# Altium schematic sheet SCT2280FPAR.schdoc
size 127 x 101 mm
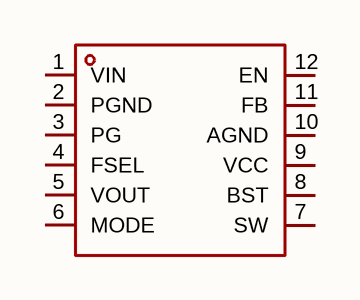
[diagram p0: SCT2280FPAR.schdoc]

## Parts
U?  sct2280fpar  [QFN-12_L2.0-W3.0-P0.50-BL]  (value not drawn)

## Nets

Not connected (* = marked no-connect by the designer): U? 1(VIN) 2(PGND) 3(PG) 4(FSEL) 5(VOUT) 6(MODE) 7(SW) 8(BST) 9(VCC) 10(AGND) 11(FB) 12(EN)

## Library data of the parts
U? = sct2280fpar: 功能类型:降压型;工作电压:4.5V~18V;输出电压:600mV~7V;输出电流:8A;输出类型:可调;; Manufacturer: SCT(芯洲科技); AddInBom: yes; ModelId: 0ae59447a7924f2e9e6865042a3e138b; ModelTransform: 118.8974,80.3148,0,0,0,0,0,-4.016,0; Function: 降压型; Output Current: 8A; Frequency - Switching: 400kHz~1.2MHz; Synchronous Rectifier: 是; Number of Outputs: 1; Topology: 降压式; Quiescent Current: 130uA; Switch tube (built-in/external): 内置; Output Type: 可调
